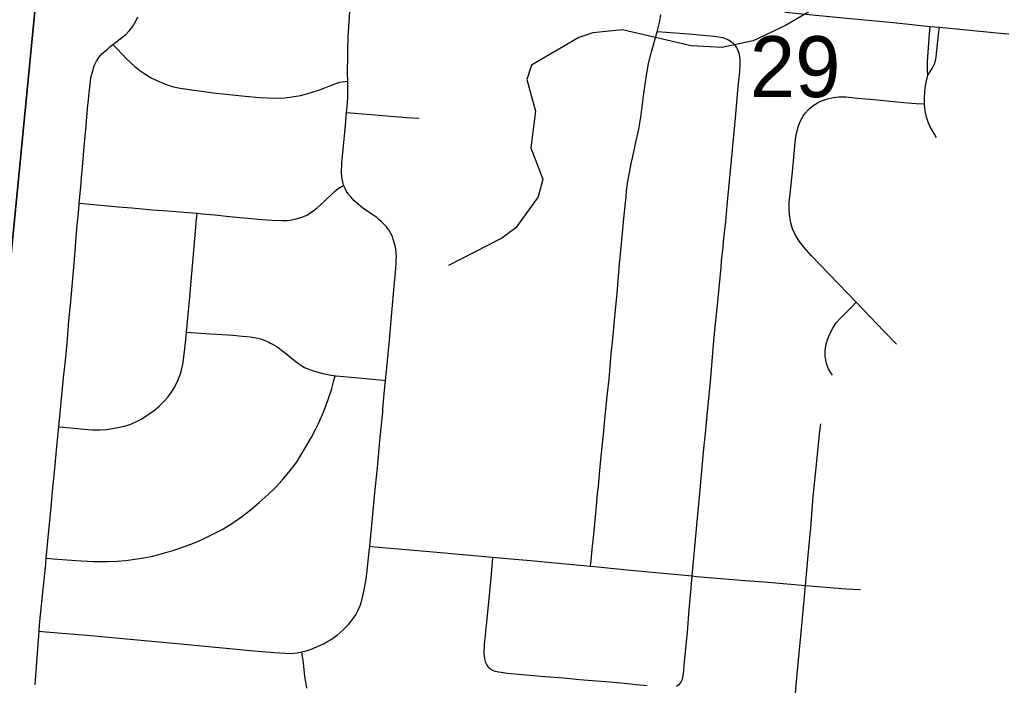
# Model space of a CAD drawing. Extents: x 0 to 34, y 0 to 22.
# Drawn here: x 24.755 to 25.43, y 13.757 to 14.215 of the extents above; entities that cross this region are included whole.
import ezdxf

# ---------------------------------------------------------------- set-up
doc = ezdxf.new("R2010")
doc.units = 0
for name, color, linetype in [('GM_X_City_Street', 7, 'Continuous'), ('GM_X_County_Road', 7, 'Continuous'), ('GM_X_Minor_River', 7, 'Continuous'), ('GM_X_Section', 7, 'Continuous'), ('GM_X_Section_Text', 7, 'Continuous')]:
    doc.layers.add(name, color=color, linetype=linetype)

msp = doc.modelspace()

# ---------------------------------------------------------------- linework, layer by layer
at = {"layer": 'GM_X_City_Street'}
for points in [[(24.76592, 13.75774), (24.76856, 13.79457), (24.76887, 13.79891), (24.77139, 13.82339), (24.77266, 13.83632), (24.77308, 13.84064), (24.77344, 13.84475), (24.77406, 13.85178), (24.77543, 13.86599), (24.7768, 13.87956), (24.77783, 13.8907), (24.77932, 13.90609), (24.78052, 13.91907), (24.78205, 13.93498), (24.78272, 13.94194), (24.78541, 13.96851), (24.78622, 13.97655), (24.78683, 13.98272), (24.78794, 13.99509), (24.789, 14.00799), (24.79007, 14.01848), (24.79218, 14.04199), (24.79328, 14.05558), (24.79401, 14.06526), (24.79478, 14.07315), (24.79576, 14.08426), (24.79616, 14.08863), (24.79738, 14.10214), (24.79772, 14.10636), (24.79807, 14.11061), (24.79946, 14.12722), (24.80077, 14.14207), (24.80184, 14.15361), (24.80353, 14.17045), (24.80414, 14.17466), (24.80516, 14.17879), (24.80641, 14.18293), (24.80795, 14.1861), (24.80962, 14.18858), (24.81194, 14.19136), (24.81385, 14.19303), (24.81545, 14.19452), (24.81704, 14.19593), (24.81925, 14.19766), (24.82129, 14.1992), (24.82515, 14.20215), (24.82808, 14.20455), (24.83075, 14.20731), (24.83306, 14.21037), (24.83498, 14.21371), (24.83626, 14.21664)], [(24.76856, 13.79457), (24.77326, 13.79416), (24.80131, 13.79167), (24.86077, 13.78619), (24.91642, 13.78106), (24.93007, 13.77979), (24.93815, 13.77936), (24.94199, 13.77926), (24.94579, 13.77962), (24.9491, 13.78023), (24.95195, 13.78096), (24.95509, 13.78203), (24.9599, 13.78394), (24.96434, 13.78615), (24.96615, 13.78716), (24.9668, 13.78746), (24.96866, 13.78861), (24.97324, 13.79182), (24.97754, 13.7955), (24.98111, 13.79909), (24.98393, 13.80251), (24.98607, 13.80567), (24.98788, 13.80903), (24.98932, 13.81254), (24.99062, 13.81677), (24.99201, 13.8229), (24.99322, 13.83028), (24.99396, 13.83618), (24.9952, 13.84728), (24.99573, 13.85283), (24.99944, 13.89191), (25.00107, 13.9067), (25.00275, 13.92526), (25.00462, 13.94494), (25.0048, 13.9474), (25.00586, 13.96023), (25.00655, 13.96683), (25.0072, 13.97306), (25.0092, 13.99454), (25.01088, 14.01359), (25.01259, 14.03141), (25.01364, 14.04366), (25.01386, 14.04687), (25.01397, 14.04924), (25.01413, 14.05143), (25.01397, 14.05443), (25.01368, 14.05691), (25.01324, 14.05918), (25.01259, 14.06159), (25.01193, 14.06385), (25.01127, 14.06568), (25.01018, 14.0678), (25.00878, 14.07021), (25.00718, 14.07232), (25.00543, 14.07422), (25.00353, 14.07605), (25.00207, 14.07744), (25.00053, 14.07882), (24.99856, 14.08021), (24.99527, 14.08217), (24.99078, 14.0854), (24.98791, 14.08773), (24.98497, 14.09029), (24.98264, 14.09285), (24.98084, 14.09512), (24.97979, 14.09672), (24.97898, 14.09818), (24.97811, 14.10008), (24.97785, 14.10093), (24.97753, 14.10193), (24.97716, 14.10329), (24.97672, 14.10534), (24.9765, 14.10738), (24.97636, 14.1095), (24.97643, 14.1114), (24.9765, 14.11388), (24.97665, 14.11652), (24.97746, 14.12539), (24.97912, 14.14205), (24.97985, 14.15099), (24.98014, 14.15446), (24.98046, 14.15819), (24.98059, 14.16131), (24.98067, 14.16881), (24.98058, 14.17232), (24.98044, 14.1781), (24.98065, 14.18982), (24.98069, 14.19045), (24.98074, 14.19355), (24.981, 14.20346), (24.98115, 14.20624), (24.98213, 14.22005)], [(25.14738, 13.83927), (25.1478, 13.84318), (25.14865, 13.85082), (25.14979, 13.86099), (25.15081, 13.87308), (25.15176, 13.88292), (25.15234, 13.88903), (25.15282, 13.8939), (25.15369, 13.90249), (25.15473, 13.91486), (25.15633, 13.92968), (25.15722, 13.9402), (25.15911, 13.95797), (25.16017, 13.96773), (25.16168, 13.98504), (25.16244, 13.99308), (25.16459, 14.01533), (25.16566, 14.02646), (25.16712, 14.04439), (25.16823, 14.05605), (25.17063, 14.08046), (25.17187, 14.09325), (25.17219, 14.09693), (25.17243, 14.09876), (25.17264, 14.1006), (25.17313, 14.10363), (25.17385, 14.10724), (25.17547, 14.11575), (25.17642, 14.12061), (25.17888, 14.13152), (25.18054, 14.13945), (25.18218, 14.14928), (25.18414, 14.16406), (25.18556, 14.17498), (25.18652, 14.18058), (25.1875, 14.1854), (25.18929, 14.19258), (25.19323, 14.2064), (25.19371, 14.20811), (25.19495, 14.2136), (25.19579, 14.21828)], [(25.37915, 14.17664), (25.37897, 14.17975), (25.37889, 14.18197), (25.37907, 14.18562), (25.37949, 14.19227), (25.3804, 14.20473), (25.38079, 14.2101)], [(25.37915, 14.17664), (25.38137, 14.17984), (25.38218, 14.18102), (25.38299, 14.18244), (25.3834, 14.18334), (25.38392, 14.18477), (25.38427, 14.18595), (25.38463, 14.1875), (25.38495, 14.18912), (25.38662, 14.20455), (25.38716, 14.2095)], [(25.20754, 13.75732), (25.20849, 13.75815), (25.20942, 13.75932), (25.2101, 13.76054), (25.21057, 13.76155), (25.21088, 13.76273), (25.21113, 13.76401), (25.21137, 13.76578), (25.21158, 13.76743), (25.21185, 13.77108), (25.21413, 13.79391), (25.21528, 13.80932), (25.2165, 13.82398), (25.21718, 13.83252), (25.22078, 13.86985), (25.22228, 13.88654), (25.22348, 13.89952), (25.22515, 13.91741), (25.22559, 13.92234), (25.22613, 13.92788), (25.22758, 13.94269), (25.23002, 13.96867), (25.23197, 13.99157), (25.23292, 14.00134), (25.23442, 14.01613), (25.23716, 14.04454), (25.23752, 14.04887), (25.23834, 14.05628), (25.23913, 14.0643), (25.24036, 14.076), (25.2414, 14.08702), (25.24291, 14.10368), (25.24694, 14.14692), (25.24816, 14.1605), (25.24845, 14.16359), (25.24889, 14.16852), (25.24949, 14.1747), (25.24992, 14.179), (25.25031, 14.18452), (25.25034, 14.18622), (25.25024, 14.18753), (25.25009, 14.18906), (25.24983, 14.19047), (25.24941, 14.19203), (25.24894, 14.19328), (25.24839, 14.19442), (25.24788, 14.19533), (25.24717, 14.19638), (25.24653, 14.19723), (25.2455, 14.19823), (25.24438, 14.1992), (25.24331, 14.19994), (25.24223, 14.20058), (25.2414, 14.20102), (25.24035, 14.20145), (25.23911, 14.2019), (25.23794, 14.2022), (25.23672, 14.20243), (25.23545, 14.20264), (25.2321, 14.20309), (25.21974, 14.20424), (25.21481, 14.20466), (25.21171, 14.20489), (25.19935, 14.2059), (25.19323, 14.2064)], [(24.81925, 14.19766), (24.82209, 14.19466), (24.82852, 14.18786), (24.83422, 14.18253), (24.83765, 14.17983), (24.84116, 14.17742), (24.84517, 14.17501), (24.84933, 14.17296), (24.85262, 14.1715), (24.85664, 14.16982), (24.86007, 14.16872), (24.86555, 14.16756), (24.88805, 14.16434), (24.91011, 14.16208), (24.9199, 14.16127), (24.92515, 14.16098), (24.93268, 14.16084), (24.93743, 14.16106), (24.94247, 14.16157), (24.94816, 14.16252), (24.95474, 14.16434), (24.96198, 14.16665), (24.96372, 14.16732), (24.96718, 14.16871), (24.96892, 14.16938), (24.97066, 14.17007), (24.973, 14.17099), (24.97519, 14.17165), (24.97694, 14.17187), (24.98058, 14.17232)], [(25.38511, 14.13352), (25.38378, 14.13611), (25.38067, 14.14147), (25.37936, 14.14428), (25.3782, 14.14781), (25.37733, 14.15207), (25.3769, 14.15678), (25.37692, 14.16134), (25.37738, 14.16784), (25.37826, 14.17255), (25.37915, 14.17664)], [(25.35772, 13.99178), (25.34902, 14.00064), (25.33006, 14.02054), (25.31154, 14.03961), (25.29906, 14.05258), (25.29418, 14.05814), (25.29086, 14.06254), (25.2883, 14.0667), (25.28627, 14.07108), (25.28497, 14.07513), (25.28428, 14.07869), (25.28382, 14.08353), (25.28394, 14.08903), (25.28482, 14.09703), (25.28615, 14.11003), (25.28837, 14.1329), (25.28919, 14.13771), (25.29034, 14.14179), (25.29171, 14.14516), (25.29349, 14.14829), (25.29526, 14.15072), (25.29727, 14.15294), (25.3, 14.15531), (25.30302, 14.1573), (25.30625, 14.15894), (25.31022, 14.1604), (25.31434, 14.16129), (25.31795, 14.16162), (25.32284, 14.16157), (25.33084, 14.16078), (25.342, 14.15976), (25.36243, 14.15778), (25.37115, 14.15717), (25.3769, 14.15678)], [(24.97985, 14.15099), (24.98571, 14.15049), (24.99057, 14.15007), (24.99668, 14.14959), (25.01283, 14.14822), (25.02125, 14.1475), (25.02974, 14.1469)], [(24.79616, 14.08863), (24.79854, 14.08841), (24.82301, 14.08612), (24.83228, 14.08529), (24.84652, 14.08408), (24.85705, 14.08325), (24.87067, 14.08219), (24.87712, 14.08165), (24.88057, 14.08135), (24.88923, 14.08055), (24.89726, 14.07975), (24.90653, 14.07875), (24.91208, 14.07823), (24.91888, 14.07766), (24.92194, 14.07738), (24.92873, 14.07687), (24.93571, 14.07664), (24.939, 14.07679), (24.94207, 14.07715), (24.94513, 14.07774), (24.94754, 14.07843), (24.94983, 14.07912), (24.95247, 14.08042), (24.95501, 14.08194), (24.95695, 14.08337), (24.95937, 14.08523), (24.96172, 14.08719), (24.96438, 14.08965), (24.96657, 14.09179), (24.9692, 14.09441), (24.97143, 14.09673), (24.97406, 14.0987), (24.97785, 14.10093)], [(24.78205, 13.93498), (24.78488, 13.93471), (24.79267, 13.93397), (24.79949, 13.93332), (24.80526, 13.93296), (24.81052, 13.93293), (24.81479, 13.9332), (24.81904, 13.93376), (24.82266, 13.93441), (24.82803, 13.93568), (24.83148, 13.93682), (24.83594, 13.9388), (24.83864, 13.94021), (24.84333, 13.94309), (24.84779, 13.94631), (24.85104, 13.9491), (24.85452, 13.95253), (24.8569, 13.95531), (24.85947, 13.95872), (24.86169, 13.96235), (24.86385, 13.96673), (24.86565, 13.97127), (24.86668, 13.97477), (24.86757, 13.97919), (24.86868, 13.98879), (24.86934, 13.995), (24.86981, 13.99987), (24.87195, 14.02178), (24.8756, 14.06414), (24.87677, 14.07758), (24.87712, 14.08165)], [(25.31361, 13.9705), (25.31254, 13.97203), (25.31099, 13.97474), (25.30973, 13.97769), (25.30904, 13.98062), (25.3087, 13.98371), (25.30878, 13.98745), (25.30943, 13.99177), (25.31043, 13.99537), (25.3118, 13.99885), (25.31386, 14.0027), (25.31633, 14.0063), (25.31915, 14.00963), (25.32665, 14.01713), (25.33006, 14.02054)], [(24.86981, 13.99987), (24.87313, 13.99966), (24.88642, 13.99881), (24.90187, 13.9978), (24.90801, 13.99724), (24.9112, 13.997), (24.91355, 13.99675), (24.91636, 13.99635), (24.91891, 13.99575), (24.92058, 13.99529), (24.9224, 13.99472), (24.92429, 13.99404), (24.92633, 13.99316), (24.92764, 13.99247), (24.92901, 13.99175), (24.93049, 13.99081), (24.9321, 13.98979), (24.93362, 13.98871), (24.9351, 13.98766), (24.93878, 13.98475), (24.94286, 13.98152), (24.94696, 13.97824), (24.94917, 13.97679), (24.95092, 13.97578), (24.95268, 13.97493), (24.95499, 13.97403), (24.95704, 13.97338), (24.95944, 13.97262), (24.96187, 13.97192), (24.96437, 13.97127), (24.96693, 13.97082), (24.96933, 13.97041), (24.972, 13.97008), (24.97273, 13.96999), (24.98794, 13.96864), (25.00274, 13.96721), (25.00655, 13.96683)], [(24.77344, 13.84475), (24.77846, 13.84428), (24.79377, 13.84308), (24.80562, 13.84239), (24.81116, 13.84241), (24.81612, 13.84238), (24.82219, 13.84267), (24.82803, 13.84315), (24.83441, 13.84401), (24.84059, 13.84496), (24.84548, 13.84593), (24.85086, 13.84717), (24.86041, 13.84986), (24.8691, 13.85289), (24.87275, 13.8543), (24.8768, 13.85591), (24.88108, 13.85782), (24.88389, 13.85909), (24.89433, 13.86444), (24.90146, 13.86867), (24.90764, 13.87304), (24.91362, 13.87761), (24.91986, 13.88291), (24.92604, 13.88842), (24.93103, 13.89317), (24.93558, 13.89837), (24.94116, 13.90488), (24.94532, 13.9104), (24.94841, 13.91537), (24.95098, 13.91964), (24.9556, 13.92786), (24.95842, 13.9331), (24.96044, 13.93713), (24.96393, 13.94506), (24.96723, 13.95366), (24.96964, 13.96132), (24.97112, 13.96682), (24.972, 13.97008)], [(25.28772, 13.74624), (25.28872, 13.75732), (25.29015, 13.77208), (25.29114, 13.78191), (25.29205, 13.79112), (25.29435, 13.81577), (25.29526, 13.82591), (25.29671, 13.844), (25.29786, 13.85636), (25.29875, 13.8656), (25.29975, 13.87792), (25.30053, 13.88717), (25.30241, 13.90685), (25.30359, 13.91849), (25.30501, 13.93203), (25.30558, 13.93691)], [(24.99573, 13.85283), (24.99914, 13.85255), (25.03923, 13.84914), (25.08019, 13.84546), (25.09276, 13.84433), (25.10368, 13.84342), (25.12052, 13.84182), (25.14738, 13.83927), (25.15008, 13.83901), (25.17495, 13.83651), (25.20491, 13.8337), (25.21718, 13.83252), (25.22035, 13.8322), (25.25362, 13.82939), (25.26966, 13.82829), (25.29526, 13.82591), (25.32298, 13.82368), (25.333, 13.82307)], [(25.08019, 13.84546), (25.07986, 13.84165), (25.07874, 13.82864), (25.07714, 13.81217), (25.07581, 13.79874), (25.07471, 13.7895), (25.07454, 13.78759), (25.07434, 13.78535), (25.07425, 13.7832), (25.07413, 13.78096), (25.0742, 13.77939), (25.07435, 13.77737), (25.07454, 13.77607), (25.07484, 13.77453), (25.07507, 13.77368), (25.07537, 13.77296), (25.07571, 13.77209), (25.07625, 13.77118), (25.07688, 13.77031)], [(24.95239, 13.7554), (24.95122, 13.76394), (24.9501, 13.77255), (24.9491, 13.78023)], [(25.07688, 13.77031), (25.07781, 13.76938), (25.07845, 13.7688), (25.07917, 13.7683), (25.07997, 13.76782), (25.08108, 13.76733), (25.08221, 13.76698), (25.08416, 13.76654), (25.08601, 13.76625), (25.09012, 13.76572), (25.09549, 13.76516), (25.11337, 13.76368), (25.12885, 13.76244), (25.13996, 13.7613), (25.1578, 13.75991), (25.1684, 13.75897), (25.17875, 13.7579), (25.18642, 13.75727)], [(25.20646, 13.75674), (25.20754, 13.75732)]]:
    msp.add_lwpolyline(points, dxfattribs=at)
at = {"layer": 'GM_X_County_Road'}
for points in [[(25.28098, 14.21979), (25.28593, 14.21932), (25.29995, 14.21797), (25.32098, 14.21604), (25.35559, 14.21268), (25.38079, 14.2101)], [(25.38079, 14.2101), (25.38716, 14.2095), (25.42673, 14.20573), (25.44525, 14.20394), (25.47521, 14.20105), (25.49892, 14.19921), (25.52182, 14.1971), (25.54225, 14.19519), (25.5695, 14.19281), (25.58619, 14.19117), (25.61028, 14.1887), (25.62079, 14.18773), (25.6387, 14.18601), (25.66404, 14.18357), (25.68259, 14.18188), (25.70784, 14.17932)]]:
    msp.add_lwpolyline(points, dxfattribs=at)
at = {"layer": 'GM_X_Minor_River'}
msp.add_lwpolyline([(25.45836, 14.25488), (25.39712, 14.24663), (25.37457, 14.23798), (25.32101, 14.23414), (25.28146, 14.21064), (25.25925, 14.20009), (25.23791, 14.19559), (25.2167, 14.19678), (25.16949, 14.2076), (25.14897, 14.20574), (25.13943, 14.20252), (25.1068, 14.18344), (25.10357, 14.17364), (25.10958, 14.15188), (25.10642, 14.12652), (25.11472, 14.10509), (25.11144, 14.09301), (25.09622, 14.07168), (25.08659, 14.06467), (25.04979, 14.04567)], dxfattribs=at)
at = {"layer": 'GM_X_Section'}
for points in [[(24.8195, 14.77309), (24.71962, 13.7501), (23.73099, 13.84446), (23.81234, 14.84657)], [(25.86182, 14.67437), (25.76091, 13.65822), (24.71962, 13.7501), (24.8195, 14.77309)]]:
    msp.add_lwpolyline(points, close=True, dxfattribs=at)

# ---------------------------------------------------------------- texts
at = {"layer": 'GM_X_Section_Text'}
msp.add_text('29', height=0.041856, rotation=0.00001, dxfattribs=at).set_placement((25.25691, 14.16146))

doc.saveas('drawing.dxf')
